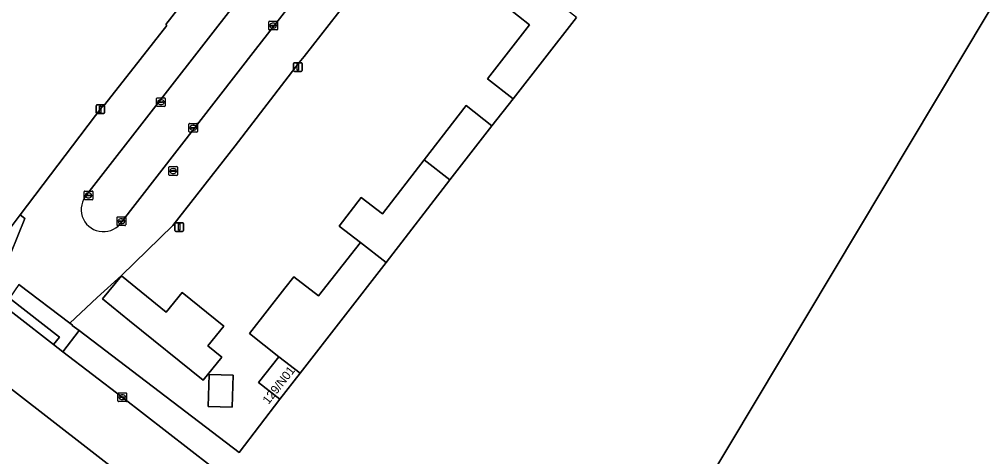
# Model space of a CAD drawing. Extents: x 159451 to 160664, y 388402 to 389723.
# Drawn here: x 160226.5 to 160338, y 389285.1 to 389335.6 of the extents above; entities that cross this region are included whole.
import ezdxf

# ---------------------------------------------------------------- set-up
doc = ezdxf.new("R2010")
doc.units = 0
for name, color, linetype in [('IMGEO_Brandkraan', 7, 'Continuous'), ('IMGEO_Erf', 7, 'Continuous'), ('IMGEO_Groenvoorziening', 7, 'Continuous'), ('IMGEO_Kolk', 7, 'Continuous'), ('IMGEO_Lichtmast', 7, 'Continuous'), ('IMGEO_Loofbos', 7, 'Continuous'), ('IMGEO_Pand', 7, 'Continuous'), ('IMGEO_Pand_nummerreeks', 7, 'Continuous'), ('IMGEO_Parkeervlak_open', 7, 'Continuous'), ('IMGEO_Rijbaan_lokaal_gesloten', 7, 'Continuous'), ('IMGEO_Rijbaan_lokaal_open', 7, 'Continuous')]:
    doc.layers.add(name, color=color, linetype=linetype)

msp = doc.modelspace()

# ---------------------------------------------------------------- linework, layer by layer
at = {"layer": 'IMGEO_Brandkraan'}
for p, q in [((160243.79, 389318.59), (160244.64, 389318.59)), ((160243.71, 389317.66), (160243.71, 389318.51)), ((160244.64, 389317.58), (160243.79, 389317.58)), ((160243.97, 389318.08), (160243.97, 389318.09)), ((160244.41, 389318.04), (160244.01, 389318.04)), ((160244.02, 389318.13), (160244.41, 389318.13)), ((160244.2, 389318.36), (160244.23, 389318.36)), ((160244.22, 389317.81), (160244.2, 389317.81)), ((160244.46, 389318.09), (160244.46, 389318.08)), ((160244.71, 389318.51), (160244.71, 389317.66))]:
    msp.add_line(p, q, dxfattribs=at)
for points in [[(160243.79, 389318.59), (160244.64, 389318.59)], [(160243.71, 389317.66), (160243.71, 389318.51)], [(160244.64, 389317.58), (160243.79, 389317.58)], [(160244.71, 389318.51), (160244.71, 389317.66)]]:
    msp.add_lwpolyline(points, dxfattribs=at)
for centre, radius, start, end in [((160243.79, 389318.51), 0.0765, 91.552, 178.448), ((160243.79, 389318.51), 0.0765, 91.552, 178.448), ((160244.64, 389318.51), 0.0765, 1.552, 88.448), ((160244.64, 389318.51), 0.0765, 1.552, 88.448), ((160243.79, 389317.66), 0.0765, 181.552, 268.448), ((160243.79, 389317.66), 0.0765, 181.552, 268.448), ((160244.01, 389318.09), 0.0403, 85.8775, 175.7526), ((160244.01, 389318.08), 0.0366, 178.938, 274.7102), ((160244.42, 389318.09), 0.0386, 1.7309, 96.639), ((160244.41, 389318.08), 0.043, 264.8664, 352.4533), ((160244.64, 389317.66), 0.0765, 271.552, 358.448), ((160244.64, 389317.66), 0.0765, 271.552, 358.448)]:
    msp.add_arc(centre, radius, start, end, dxfattribs=at)
for centre, major_axis, ratio, start_param, end_param in [((160244.2, 389318.08), (-0.387, 0.002), 0.722429, 4.712389, 7.853982), ((160244.22, 389318.08), (-0.39, 0.002), 0.717154, 1.570796, 4.712389)]:
    msp.add_ellipse(centre, major_axis=major_axis, ratio=ratio, start_param=start_param, end_param=end_param, dxfattribs=at)
at = {"layer": 'IMGEO_Erf'}
for points in [[(160222.96, 389308.25), (160226.58, 389313.02), (160236.11, 389325.61), (160236.18, 389325.56), (160238.85, 389328.97), (160243.48, 389334.89), (160243.37, 389334.98), (160250.65, 389344.36)], [(160264.1, 389337.46), (160259.3, 389331.31), (160258.74, 389330.6), (160251.36, 389320.99), (160244.16, 389311.78), (160238.24, 389306.03), (160235.43, 389303.49), (160232.31, 389300.51), (160232.59, 389300.3), (160232.56, 389300.27), (160233.35, 389299.67), (160251.82, 389285.59), (160256.51, 389291.74), (160254.06, 389293.67), (160256.4, 389296.66), (160252.99, 389299.33), (160257.07, 389304.55), (160258.12, 389305.89), (160260.95, 389303.67), (160265.23, 389309.1), (160265.8, 389309.83), (160263.36, 389311.72), (160265.9, 389315.03), (160268.34, 389313.14), (160273.16, 389319.38), (160278, 389325.64), (160280.95, 389323.29), (160283.42, 389326.4), (160280.45, 389328.72), (160285.31, 389334.95), (160282.77, 389336.94)]]:
    msp.add_lwpolyline(points, dxfattribs=at)
for points in [[(160245.25, 389304.08), (160250.05, 389300.19), (160248.21, 389297.92), (160249.81, 389296.62), (160247.65, 389293.94), (160239.17, 389300.81), (160236.07, 389303.32), (160238.23, 389305.99), (160243.41, 389301.8)], [(160248.25, 389290.92), (160248.35, 389294.59), (160251.11, 389294.52), (160251.02, 389290.85)]]:
    msp.add_lwpolyline(points, close=True, dxfattribs=at)
at = {"layer": 'IMGEO_Groenvoorziening'}
for points in [[(160296.48, 389266.59), (160370.8, 389390.89)], [(160290.72, 389335.81), (160283.42, 389326.4), (160280.95, 389323.29), (160276.11, 389317.05), (160268.75, 389307.54), (160258.84, 389294.75), (160256.51, 389291.74), (160251.82, 389285.59), (160233.35, 389299.67), (160231.48, 389297.23), (160238.34, 389291.99), (160261.52, 389273.97)], [(160206.57, 389283.54), (160243.22, 389261.1), (160249.57, 389256.04), (160248.7, 389258.56), (160256.12, 389260.14), (160257.39, 389259.12), (160260.16, 389262.02), (160261.62, 389263.55), (160257.09, 389268.4), (160221.21, 389296.26)]]:
    msp.add_lwpolyline(points, dxfattribs=at)
at = {"layer": 'IMGEO_Kolk'}
for p, q in [((160255.23, 389334.43), (160255.23, 389335.28)), ((160255.3, 389335.36), (160256.16, 389335.36)), ((160256.23, 389335.28), (160256.23, 389334.43)), ((160256.16, 389334.36), (160255.3, 389334.36)), ((160255.49, 389334.85), (160255.49, 389334.86)), ((160255.53, 389334.9), (160255.93, 389334.9)), ((160255.93, 389334.81), (160255.53, 389334.81)), ((160255.74, 389334.58), (160255.71, 389334.58)), ((160255.72, 389335.14), (160255.74, 389335.14)), ((160255.97, 389334.86), (160255.97, 389334.85)), ((160242.3, 389325.6), (160242.3, 389326.45)), ((160242.37, 389326.52), (160243.22, 389326.52)), ((160243.3, 389326.45), (160243.3, 389325.6)), ((160243.22, 389325.52), (160242.37, 389325.52)), ((160242.55, 389326.02), (160242.55, 389326.03)), ((160242.99, 389325.98), (160242.59, 389325.98)), ((160242.6, 389326.07), (160242.99, 389326.07)), ((160242.78, 389326.3), (160242.81, 389326.3)), ((160242.81, 389325.74), (160242.78, 389325.74)), ((160243.04, 389326.03), (160243.04, 389326.02)), ((160246.02, 389322.65), (160246.02, 389323.5)), ((160246.1, 389323.58), (160246.95, 389323.58)), ((160246.28, 389323.07), (160246.28, 389323.08)), ((160246.72, 389323.03), (160246.32, 389323.03)), ((160246.33, 389323.12), (160246.72, 389323.12)), ((160246.51, 389323.36), (160246.54, 389323.36)), ((160246.77, 389323.08), (160246.77, 389323.07)), ((160247.03, 389323.5), (160247.03, 389322.65)), ((160246.95, 389322.58), (160246.1, 389322.58)), ((160246.53, 389322.8), (160246.51, 389322.8)), ((160233.94, 389314.84), (160233.94, 389315.7)), ((160234.02, 389315.77), (160234.87, 389315.77)), ((160234.2, 389315.26), (160234.2, 389315.28)), ((160234.24, 389315.31), (160234.64, 389315.31)), ((160234.64, 389315.23), (160234.24, 389315.23)), ((160234.43, 389315.55), (160234.45, 389315.55)), ((160234.68, 389315.28), (160234.68, 389315.26)), ((160234.94, 389315.7), (160234.94, 389314.84)), ((160234.87, 389314.77), (160234.02, 389314.77)), ((160234.45, 389314.99), (160234.43, 389314.99)), ((160237.73, 389311.86), (160237.73, 389312.71)), ((160237.8, 389312.78), (160238.66, 389312.78)), ((160237.99, 389312.28), (160237.99, 389312.29)), ((160238.03, 389312.33), (160238.43, 389312.33)), ((160238.42, 389312.24), (160238.03, 389312.24)), ((160238.24, 389312), (160238.21, 389312)), ((160238.22, 389312.56), (160238.24, 389312.56)), ((160238.47, 389312.29), (160238.47, 389312.28)), ((160238.73, 389312.71), (160238.73, 389311.86)), ((160238.66, 389311.78), (160237.8, 389311.78)), ((160237.84, 389291.56), (160237.84, 389292.42)), ((160237.92, 389292.49), (160238.77, 389292.49)), ((160238.1, 389291.98), (160238.1, 389292)), ((160238.14, 389292.03), (160238.54, 389292.03)), ((160238.54, 389291.95), (160238.14, 389291.95)), ((160238.33, 389292.27), (160238.35, 389292.27)), ((160238.58, 389292), (160238.58, 389291.98)), ((160238.84, 389292.42), (160238.84, 389291.56)), ((160238.77, 389291.49), (160237.92, 389291.49)), ((160238.35, 389291.71), (160238.33, 389291.71))]:
    msp.add_line(p, q, dxfattribs=at)
for points in [[(160255.23, 389334.43), (160255.23, 389335.28)], [(160255.3, 389335.36), (160256.16, 389335.36)], [(160256.23, 389335.28), (160256.23, 389334.43)], [(160256.16, 389334.36), (160255.3, 389334.36)], [(160242.3, 389325.6), (160242.3, 389326.45)], [(160242.37, 389326.52), (160243.22, 389326.52)], [(160243.3, 389326.45), (160243.3, 389325.6)], [(160243.22, 389325.52), (160242.37, 389325.52)], [(160246.02, 389322.65), (160246.02, 389323.5)], [(160246.1, 389323.58), (160246.95, 389323.58)], [(160247.03, 389323.5), (160247.03, 389322.65)], [(160246.95, 389322.58), (160246.1, 389322.58)], [(160233.94, 389314.84), (160233.94, 389315.7)], [(160234.02, 389315.77), (160234.87, 389315.77)], [(160234.94, 389315.7), (160234.94, 389314.84)], [(160234.87, 389314.77), (160234.02, 389314.77)], [(160237.73, 389311.86), (160237.73, 389312.71)], [(160237.8, 389312.78), (160238.66, 389312.78)], [(160238.73, 389312.71), (160238.73, 389311.86)], [(160238.66, 389311.78), (160237.8, 389311.78)], [(160237.84, 389291.56), (160237.84, 389292.42)], [(160237.92, 389292.49), (160238.77, 389292.49)], [(160238.84, 389292.42), (160238.84, 389291.56)], [(160238.77, 389291.49), (160237.92, 389291.49)]]:
    msp.add_lwpolyline(points, dxfattribs=at)
for centre, radius, start, end in [((160255.31, 389335.28), 0.0765, 91.552, 178.448), ((160255.31, 389335.28), 0.0765, 91.552, 178.448), ((160256.15, 389335.28), 0.0765, 1.552, 88.448), ((160256.15, 389335.28), 0.0765, 1.552, 88.448), ((160255.31, 389334.43), 0.0765, 181.552, 268.448), ((160255.31, 389334.43), 0.0765, 181.552, 268.448), ((160255.53, 389334.86), 0.0403, 85.8775, 175.7526), ((160255.52, 389334.85), 0.0366, 178.938, 274.7102), ((160255.93, 389334.86), 0.0386, 1.7309, 96.639), ((160255.93, 389334.86), 0.043, 264.8664, 352.4533), ((160256.15, 389334.43), 0.0765, 271.552, 358.448), ((160256.15, 389334.43), 0.0765, 271.552, 358.448), ((160242.37, 389326.45), 0.0765, 91.552, 178.448), ((160242.37, 389326.45), 0.0765, 91.552, 178.448), ((160243.22, 389326.45), 0.0765, 1.552, 88.448), ((160243.22, 389326.45), 0.0765, 1.552, 88.448), ((160242.37, 389325.6), 0.0765, 181.552, 268.448), ((160242.37, 389325.6), 0.0765, 181.552, 268.448), ((160242.59, 389326.03), 0.0403, 85.8775, 175.7526), ((160242.59, 389326.02), 0.0366, 178.938, 274.7102), ((160243, 389326.03), 0.0386, 1.7309, 96.639), ((160243, 389326.02), 0.043, 264.8664, 352.4533), ((160243.22, 389325.6), 0.0765, 271.552, 358.448), ((160243.22, 389325.6), 0.0765, 271.552, 358.448), ((160246.1, 389323.5), 0.0765, 91.552, 178.448), ((160246.1, 389323.5), 0.0765, 91.552, 178.448), ((160246.32, 389323.08), 0.0403, 85.8775, 175.7526), ((160246.32, 389323.07), 0.0366, 178.938, 274.7102), ((160246.73, 389323.08), 0.0386, 1.7309, 96.639), ((160246.72, 389323.08), 0.043, 264.8664, 352.4533), ((160246.95, 389323.5), 0.0765, 1.552, 88.448), ((160246.95, 389323.5), 0.0765, 1.552, 88.448), ((160246.1, 389322.65), 0.0765, 181.552, 268.448), ((160246.1, 389322.65), 0.0765, 181.552, 268.448), ((160246.95, 389322.65), 0.0765, 271.552, 358.448), ((160246.95, 389322.65), 0.0765, 271.552, 358.448), ((160234.02, 389315.69), 0.0765, 91.552, 178.448), ((160234.02, 389315.69), 0.0765, 91.552, 178.448), ((160234.24, 389315.27), 0.0403, 85.8775, 175.7526), ((160234.24, 389315.26), 0.0366, 178.938, 274.7102), ((160234.65, 389315.27), 0.0386, 1.7309, 96.639), ((160234.64, 389315.27), 0.043, 264.8664, 352.4533), ((160234.87, 389315.69), 0.0765, 1.552, 88.448), ((160234.87, 389315.69), 0.0765, 1.552, 88.448), ((160234.02, 389314.85), 0.0765, 181.552, 268.448), ((160234.02, 389314.85), 0.0765, 181.552, 268.448), ((160234.87, 389314.85), 0.0765, 271.552, 358.448), ((160234.87, 389314.85), 0.0765, 271.552, 358.448), ((160237.8, 389312.71), 0.0765, 91.552, 178.448), ((160237.8, 389312.71), 0.0765, 91.552, 178.448), ((160237.8, 389311.86), 0.0765, 181.552, 268.448), ((160237.8, 389311.86), 0.0765, 181.552, 268.448), ((160238.03, 389312.29), 0.0403, 85.8775, 175.7526), ((160238.02, 389312.28), 0.0366, 178.938, 274.7102), ((160238.43, 389312.28), 0.043, 264.8664, 352.4533), ((160238.43, 389312.29), 0.0386, 1.7309, 96.639), ((160238.65, 389312.71), 0.0765, 1.552, 88.448), ((160238.65, 389312.71), 0.0765, 1.552, 88.448), ((160238.65, 389311.86), 0.0765, 271.552, 358.448), ((160238.65, 389311.86), 0.0765, 271.552, 358.448), ((160237.92, 389292.41), 0.0765, 91.552, 178.448), ((160237.92, 389292.41), 0.0765, 91.552, 178.448), ((160238.14, 389291.99), 0.0403, 85.8775, 175.7526), ((160238.14, 389291.98), 0.0366, 178.938, 274.7102), ((160238.55, 389291.99), 0.0386, 1.7309, 96.639), ((160238.54, 389291.99), 0.043, 264.8664, 352.4533), ((160238.77, 389292.41), 0.0765, 1.552, 88.448), ((160238.77, 389292.41), 0.0765, 1.552, 88.448), ((160237.92, 389291.56), 0.0765, 181.552, 268.448), ((160237.92, 389291.56), 0.0765, 181.552, 268.448), ((160238.77, 389291.56), 0.0765, 271.552, 358.448), ((160238.77, 389291.56), 0.0765, 271.552, 358.448)]:
    msp.add_arc(centre, radius, start, end, dxfattribs=at)
for centre, major_axis, ratio, start_param, end_param in [((160255.72, 389334.86), (-0.387, 0.002), 0.722429, 4.712389, 7.853982), ((160255.74, 389334.86), (-0.39, 0.002), 0.717154, 1.570796, 4.712389), ((160242.78, 389326.02), (-0.387, 0.002), 0.722429, 4.712389, 7.853982), ((160242.81, 389326.02), (-0.39, 0.002), 0.717154, 1.570796, 4.712389), ((160246.51, 389323.08), (-0.387, 0.002), 0.722429, 4.712389, 7.853982), ((160246.54, 389323.08), (-0.39, 0.002), 0.717154, 1.570796, 4.712389), ((160234.43, 389315.27), (-0.387, 0.002), 0.722429, 4.712389, 7.853982), ((160234.45, 389315.27), (-0.39, 0.002), 0.717154, 1.570796, 4.712389), ((160238.22, 389312.28), (-0.387, 0.002), 0.722429, 4.712389, 7.853982), ((160238.24, 389312.28), (-0.39, 0.002), 0.717154, 1.570796, 4.712389), ((160238.33, 389291.99), (-0.387, 0.002), 0.722429, 4.712389, 7.853982), ((160238.35, 389291.99), (-0.39, 0.002), 0.717154, 1.570796, 4.712389)]:
    msp.add_ellipse(centre, major_axis=major_axis, ratio=ratio, start_param=start_param, end_param=end_param, dxfattribs=at)
at = {"layer": 'IMGEO_Lichtmast'}
for p, q in [((160258.09, 389329.68), (160258.09, 389330.48)), ((160258.09, 389330.48), (160258.09, 389329.68)), ((160258.19, 389330.58), (160258.98, 389330.58)), ((160258.98, 389330.58), (160258.19, 389330.58)), ((160259.08, 389330.48), (160259.08, 389329.68)), ((160259.08, 389329.68), (160259.08, 389330.48)), ((160258.98, 389329.58), (160258.19, 389329.58)), ((160258.19, 389329.58), (160258.98, 389329.58)), ((160235.31, 389324.81), (160235.31, 389325.61)), ((160235.31, 389325.61), (160235.31, 389324.81)), ((160235.41, 389325.71), (160236.2, 389325.71)), ((160236.2, 389325.71), (160235.41, 389325.71)), ((160236.3, 389325.61), (160236.3, 389324.81)), ((160236.3, 389324.81), (160236.3, 389325.61)), ((160236.2, 389324.71), (160235.41, 389324.71)), ((160235.41, 389324.71), (160236.2, 389324.71)), ((160244.41, 389311.22), (160244.41, 389312.02)), ((160244.41, 389312.02), (160244.41, 389311.22)), ((160244.51, 389312.12), (160245.3, 389312.12)), ((160245.3, 389312.12), (160244.51, 389312.12)), ((160245.4, 389312.02), (160245.4, 389311.22)), ((160245.4, 389311.22), (160245.4, 389312.02)), ((160245.3, 389311.12), (160244.51, 389311.12)), ((160244.51, 389311.12), (160245.3, 389311.12))]:
    msp.add_line(p, q, dxfattribs=at)
for points in [[(160258.51, 389330.45), (160258.66, 389330.45), (160258.66, 389329.7), (160258.51, 389329.7), (160258.51, 389330.45)], [(160235.73, 389325.58), (160235.88, 389325.58), (160235.88, 389324.83), (160235.73, 389324.83), (160235.73, 389325.58)], [(160244.83, 389312), (160244.98, 389312), (160244.98, 389311.25), (160244.83, 389311.25), (160244.83, 389312)]]:
    msp.add_lwpolyline(points, dxfattribs=at)
for centre, start, end in [((160258.19, 389330.48), 90, 180), ((160258.19, 389330.48), 90, 180), ((160258.98, 389330.48), 0, 90), ((160258.98, 389330.48), 360, 90), ((160258.19, 389329.68), 180, 270), ((160258.19, 389329.68), 180, 270), ((160258.98, 389329.68), 270, 0), ((160258.98, 389329.68), 270, 0), ((160235.41, 389325.61), 90, 180), ((160235.41, 389325.61), 90, 180), ((160236.2, 389325.61), 0, 90), ((160236.2, 389325.61), 360, 90), ((160235.41, 389324.81), 180, 270), ((160235.41, 389324.81), 180, 270), ((160236.2, 389324.81), 270, 0), ((160236.2, 389324.81), 270, 0), ((160244.51, 389312.02), 90, 180), ((160244.51, 389312.02), 90, 180), ((160245.3, 389312.02), 0, 90), ((160245.3, 389312.02), 360, 90), ((160244.51, 389311.22), 180, 270), ((160244.51, 389311.22), 180, 270), ((160245.3, 389311.22), 270, 0), ((160245.3, 389311.22), 270, 0)]:
    msp.add_arc(centre, 0.1, start, end, dxfattribs=at)
at = {"layer": 'IMGEO_Loofbos'}
msp.add_lwpolyline([(160398.61, 389438.15), (160370.8, 389390.89), (160296.48, 389266.59), (160288.23, 389252.93), (160291.85, 389250), (160320.8, 389226.62), (160322.66, 389227.46), (160322.61, 389228.64), (160323.07, 389229.66), (160334.31, 389244.27), (160337.87, 389249.53), (160338.17, 389250), (160350.59, 389271.26), (160354.17, 389278.57), (160367.33, 389301.86), (160383.86, 389329.25), (160400.21, 389355.75), (160433.77, 389408.47), (160434.83, 389409.92), (160440.15, 389416.4)], dxfattribs=at)
at = {"layer": 'IMGEO_Pand'}
for points in [[(160290.72, 389335.81), (160285.24, 389340.1), (160282.77, 389336.94), (160285.31, 389334.95), (160280.45, 389328.72), (160283.42, 389326.4)], [(160280.95, 389323.29), (160278, 389325.64), (160273.16, 389319.38), (160276.11, 389317.05)], [(160276.11, 389317.05), (160273.16, 389319.38), (160268.34, 389313.14), (160265.9, 389315.03), (160263.36, 389311.72), (160265.8, 389309.83), (160268.75, 389307.54)], [(160268.75, 389307.54), (160265.8, 389309.83), (160265.23, 389309.1), (160260.95, 389303.67), (160258.12, 389305.89), (160257.07, 389304.55), (160252.99, 389299.33), (160256.4, 389296.66), (160258.84, 389294.75)], [(160245.25, 389304.08), (160243.41, 389301.8), (160238.23, 389305.99), (160236.07, 389303.32), (160239.17, 389300.81), (160247.65, 389293.94), (160249.81, 389296.62), (160248.21, 389297.92), (160250.05, 389300.19)], [(160258.84, 389294.75), (160256.4, 389296.66), (160254.06, 389293.67), (160256.51, 389291.74)], [(160248.25, 389290.92), (160251.02, 389290.85), (160251.11, 389294.52), (160248.35, 389294.59)]]:
    msp.add_lwpolyline(points, close=True, dxfattribs=at)
at = {"layer": 'IMGEO_Parkeervlak_open'}
for points in [[(160287.25, 389383.41), (160269.99, 389361.27), (160249.36, 389334.78), (160234.27, 389315.37)], [(160253.7, 389332.09), (160263.77, 389345.01), (160291.24, 389380.3)], [(160238.11, 389311.98), (160253.7, 389332.09)]]:
    msp.add_lwpolyline(points, dxfattribs=at)
msp.add_arc((160236.16, 389313.64), 2.56, 137.5819, 319.6251, dxfattribs=at)
at = {"layer": 'IMGEO_Rijbaan_lokaal_gesloten'}
msp.add_lwpolyline([(160227.11, 389312.6), (160226.58, 389313.02), (160222.96, 389308.25), (160220.84, 389305.5), (160221.68, 389304.85), (160224.68, 389306.6)], close=True, dxfattribs=at)
msp.add_lwpolyline([(160221.21, 389296.26), (160257.09, 389268.4), (160261.06, 389273.38), (160261.52, 389273.97), (160238.34, 389291.99), (160231.48, 389297.23), (160230.42, 389298.07), (160221.68, 389304.85)], dxfattribs=at)
at = {"layer": 'IMGEO_Rijbaan_lokaal_open'}
for points in [[(160234.27, 389315.37), (160249.36, 389334.78), (160269.99, 389361.27), (160287.25, 389383.41)], [(160244.16, 389311.78), (160251.36, 389320.99), (160258.74, 389330.6), (160259.3, 389331.31), (160264.1, 389337.46), (160266.03, 389339.93), (160273.34, 389349.35), (160280.8, 389359), (160288.25, 389368.42), (160286.53, 389369.74), (160296.57, 389382.44)], [(160291.24, 389380.3), (160263.77, 389345.01), (160253.7, 389332.09), (160238.11, 389311.98)], [(160250.65, 389344.36), (160243.37, 389334.98), (160243.48, 389334.89), (160238.85, 389328.97), (160236.18, 389325.56), (160236.11, 389325.61), (160226.58, 389313.02), (160227.11, 389312.6), (160224.68, 389306.6)], [(160226.41, 389305), (160232.31, 389300.51), (160235.43, 389303.49), (160238.24, 389306.03), (160244.16, 389311.78)], [(160221.68, 389304.85), (160230.42, 389298.07), (160231.1, 389298.92), (160225.33, 389303.41)]]:
    msp.add_lwpolyline(points, dxfattribs=at)
msp.add_lwpolyline([(160226.41, 389305), (160225.33, 389303.41), (160231.1, 389298.92), (160230.42, 389298.07), (160231.48, 389297.23), (160233.35, 389299.67), (160232.56, 389300.27), (160232.59, 389300.3), (160232.31, 389300.51)], close=True, dxfattribs=at)
msp.add_arc((160236.16, 389313.64), 2.56, 137.5819, 319.6251, dxfattribs=at)

# ---------------------------------------------------------------- texts
at = {"layer": 'IMGEO_Pand_nummerreeks'}
msp.add_text('129/N01', height=1, rotation=51.761, dxfattribs=at).set_placement((160255.2, 389291.09))

doc.saveas('drawing.dxf')
